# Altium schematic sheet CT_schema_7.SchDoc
size 411 x 381 mm
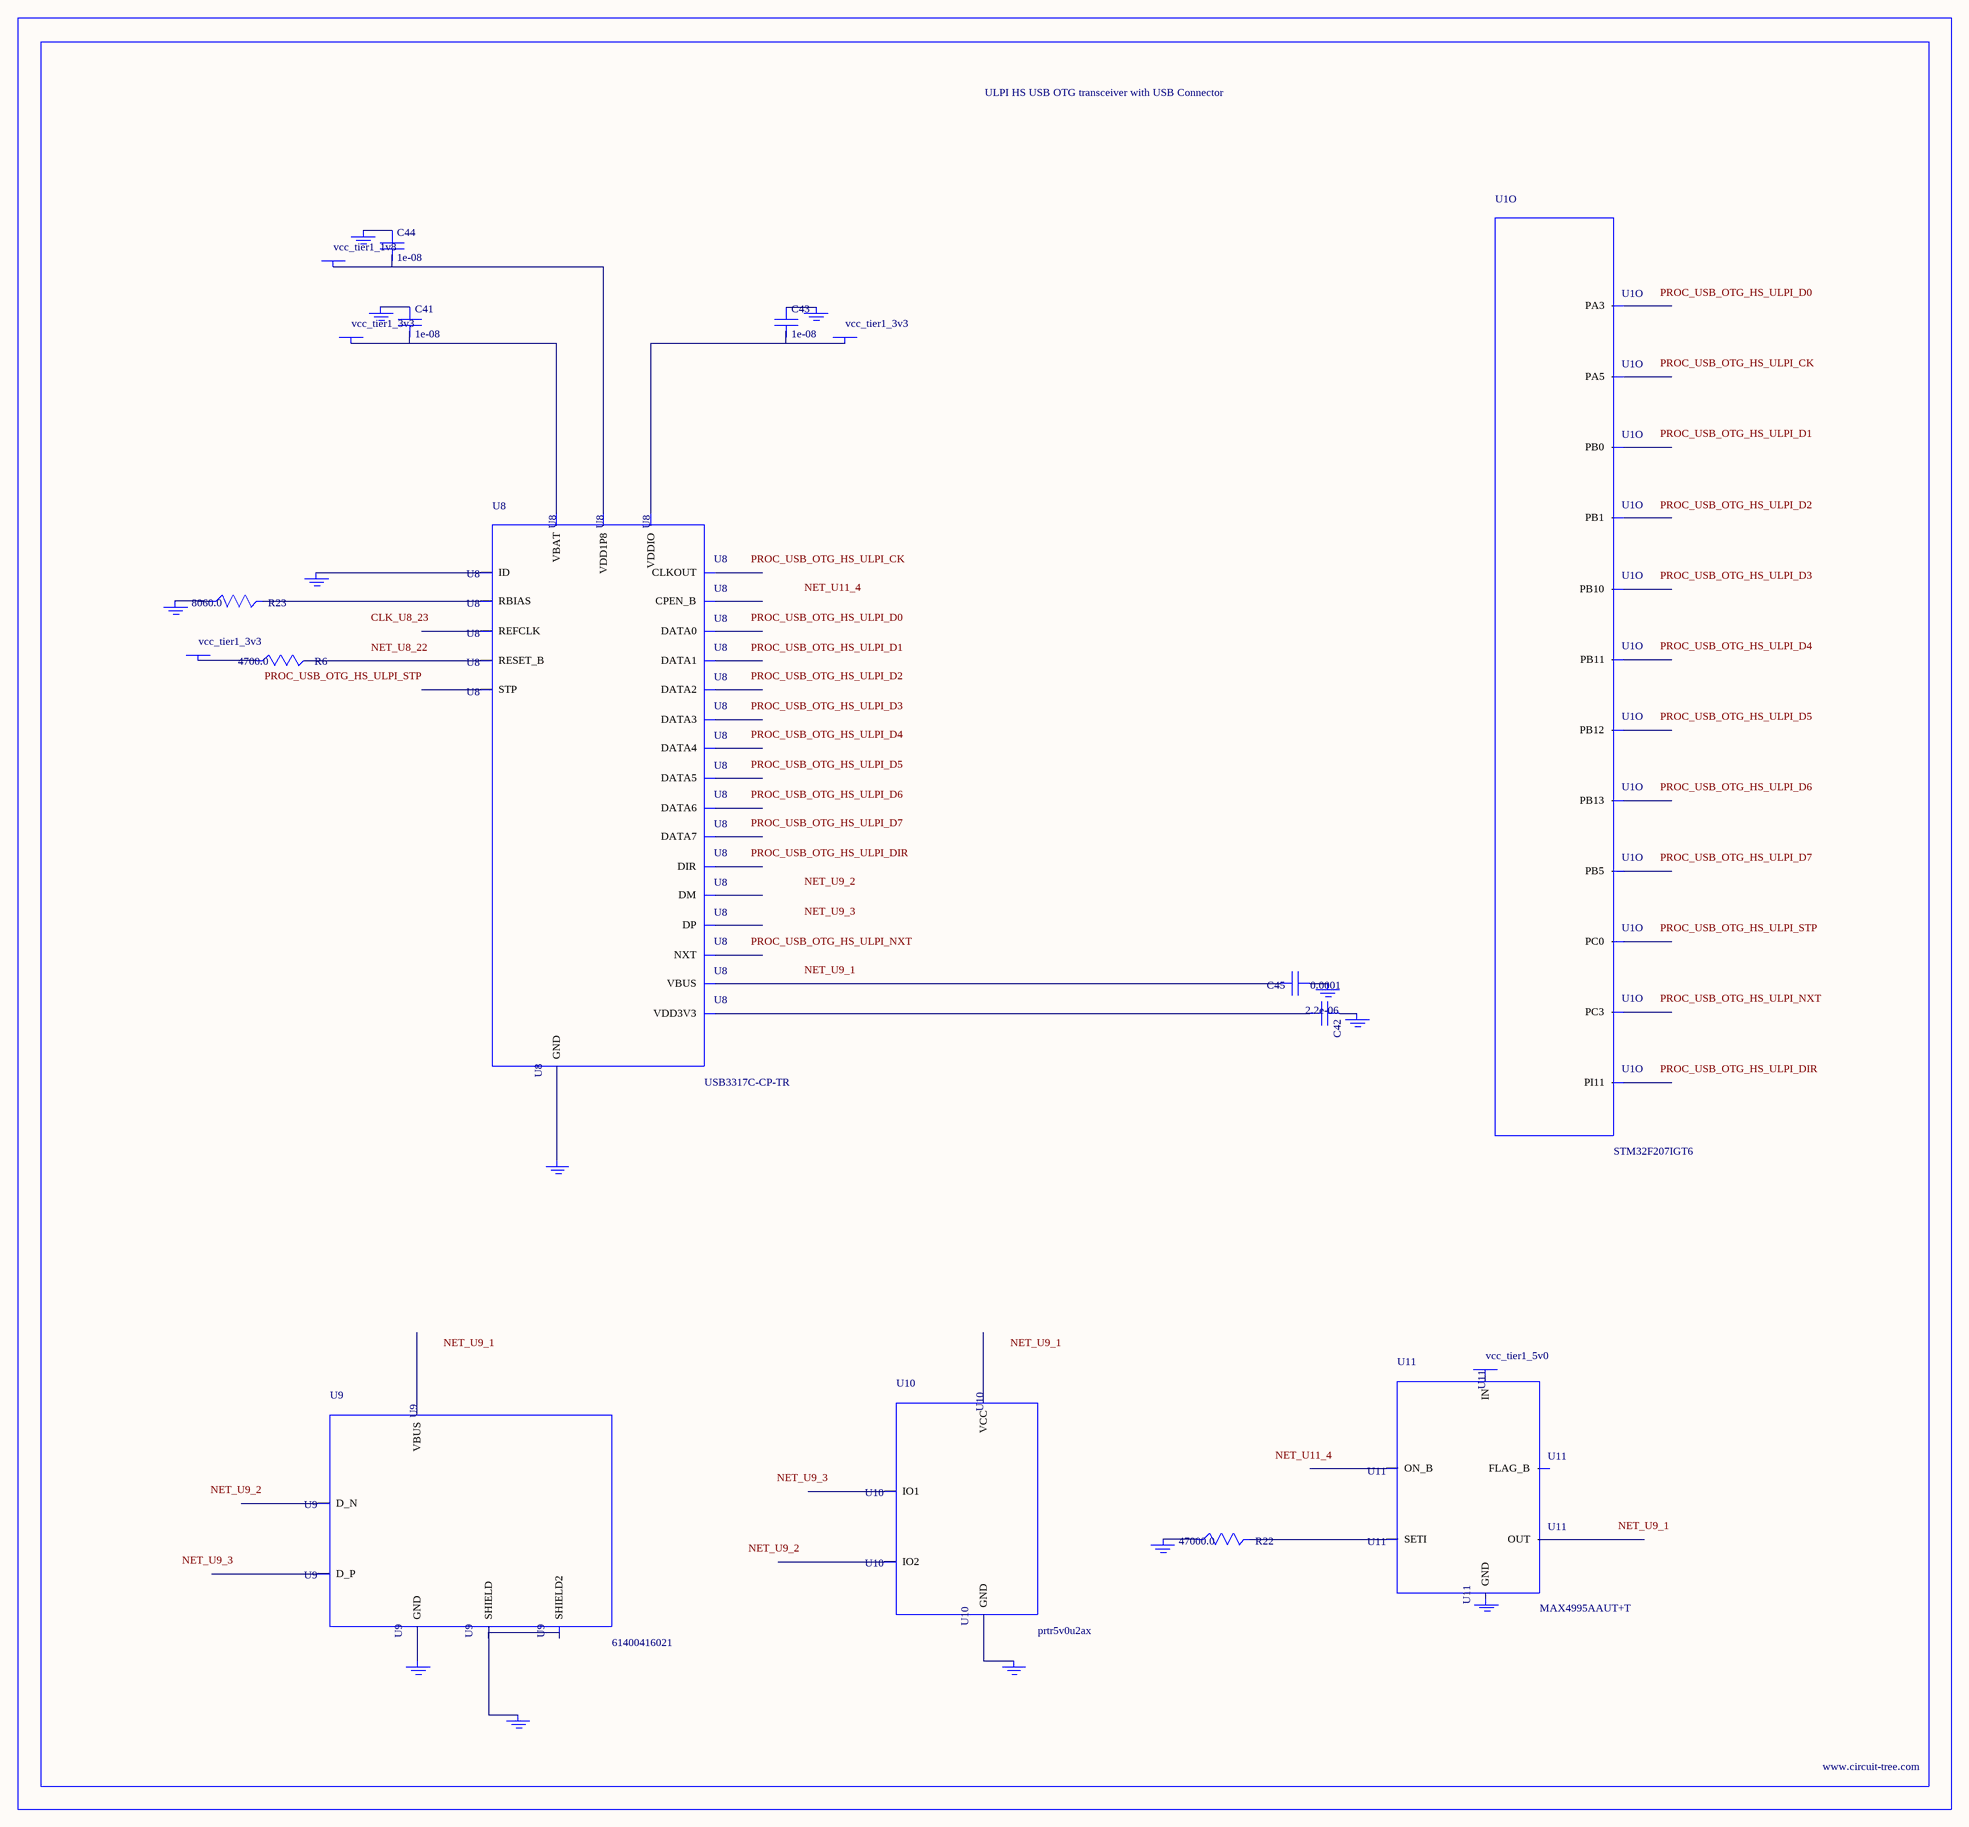
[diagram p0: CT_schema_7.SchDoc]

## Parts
BORDER6  (no value)
C41  1e-08  [C0402]
C42  2.2e-06  [C0603]
C43  1e-08  [C0402]
C44  1e-08  [C0402]
C45  0.0001  [R0603]
GND_INSTANCE_6_0  (no value)
GND_INSTANCE_6_1  (no value)
GND_INSTANCE_6_2  (no value)
GND_INSTANCE_6_3  (no value)
GND_INSTANCE_6_4  (no value)
GND_INSTANCE_6_5  (no value)
GND_INSTANCE_6_6  (no value)
GND_INSTANCE_6_7  (no value)
GND_INSTANCE_6_8  (no value)
GND_INSTANCE_6_9  (no value)
GND_INSTANCE_6_10  (no value)
GND_INSTANCE_6_11  (no value)
GND_INSTANCE_6_12  (no value)
POWER_INSTANCE_6_0  vcc_tier1_3v3
POWER_INSTANCE_6_1  vcc_tier1_3v3
POWER_INSTANCE_6_2  vcc_tier1_1v8
POWER_INSTANCE_6_3  vcc_tier1_3v3
POWER_INSTANCE_6_4  vcc_tier1_5v0
R6  4700.0  [R0603]
R22  47000.0  [R0603]
R23  8060.0  [R0603]
U1  STM32F207IGT6  [LQFP176]  (part O of 15)
U8  USB3317C-CP-TR  [QFN-24]
U9  61400416021  [USB-A-H]
U10  prtr5v0u2ax  [SOT143B]
U11  MAX4995AAUT+T  [SOT-23-6]

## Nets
NetC41_1: C41.1 GND_INSTANCE_6_2.0(GND)
NetC41_2: C41.2 POWER_INSTANCE_6_0.0(PWR) U8.3(VBAT)
NetC42_1: C42.1 GND_INSTANCE_6_3.0(GND)
NetC42_2: C42.2 U8.4(VDD3V3)
NetC43_1: C43.1 GND_INSTANCE_6_4.0(GND)
NetC43_2: C43.2 POWER_INSTANCE_6_1.0(PWR) U8.17(VDDIO)
NetC44_1: C44.1 GND_INSTANCE_6_5.0(GND)
NetC44_2: C44.2 POWER_INSTANCE_6_2.0(PWR) U8.21(VDD1P8)
NetC45_1: C45.1 GND_INSTANCE_6_1.0(GND)
NetC45_2: C45.2 U8.2(VBUS)
NetGND_INSTANCE_6_0_0: GND_INSTANCE_6_0.0(GND) U8.1(ID)
NetGND_INSTANCE_6_6_0: GND_INSTANCE_6_6.0(GND) R23.1
NetGND_INSTANCE_6_7_0: GND_INSTANCE_6_7.0(GND) U8.25(GND)
NetGND_INSTANCE_6_8_0: GND_INSTANCE_6_8.0(GND) U9.5(SHIELD) U9.6(SHIELD2)
NetGND_INSTANCE_6_9_0: GND_INSTANCE_6_9.0(GND) U9.4(GND)
NetGND_INSTANCE_6_10_0: GND_INSTANCE_6_10.0(GND) U10.1(GND)
NetGND_INSTANCE_6_11_0: GND_INSTANCE_6_11.0(GND) R22.1
NetPOWER_INSTANCE_6_3_0: POWER_INSTANCE_6_3.0(PWR) R6.1
NetR6_2: R6.2 U8.22(RESET_B)
NetR22_2: R22.2 U11.3(SETI)
NetR23_2: R23.2 U8.24(RBIAS)

Not connected (* = marked no-connect by the designer): GND_INSTANCE_6_12 0(GND); POWER_INSTANCE_6_4 0(PWR); U1 13(PI11) 32(PC0) 35(PC3) 47(PA3) 51(PA5) 56(PB0) 57(PB1) 79(PB10) 80(PB11) 92(PB12) 93(PB13) 163(PB5); U8 5(DM) 6(DP) 7(CPEN_B) 8(DATA7) 9(DATA6) 10(DATA5) 11(DATA4) 12(CLKOUT) 13(DATA3) 14(DATA2) 15(DATA1) 16(DATA0) 18(NXT) 19(DIR) 20(STP) 23(REFCLK); U9 1(VBUS) 2(D_N) 3(D_P); U10 2(IO1) 3(IO2) 4(VCC); U11 1(OUT) 2(GND) 4(ON_B) 5(IN) 6(FLAG_B)

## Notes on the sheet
- Labels drawn without touching a wire or pin: CLK_U8_23, NET_U8_22, NET_U9_1, NET_U9_2, NET_U9_3, NET_U11_4, PROC_USB_OTG_HS_ULPI_CK, PROC_USB_OTG_HS_ULPI_D0, PROC_USB_OTG_HS_ULPI_D1, PROC_USB_OTG_HS_ULPI_D2, PROC_USB_OTG_HS_ULPI_D3, PROC_USB_OTG_HS_ULPI_D4, PROC_USB_OTG_HS_ULPI_D5, PROC_USB_OTG_HS_ULPI_D6, PROC_USB_OTG_HS_ULPI_D7, PROC_USB_OTG_HS_ULPI_DIR, PROC_USB_OTG_HS_ULPI_NXT, PROC_USB_OTG_HS_ULPI_STP

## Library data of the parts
BORDER6 = BORDER_PAGE6
C41 C43 C44 = C0402C103K3RAC
C42 = C0603C225K8RACTU
C45 = C45
GND_INSTANCE_6_0-GND_INSTANCE_6_12 = GND
POWER_INSTANCE_6_0-POWER_INSTANCE_6_4 = PWR
R6 = RC0603JR-074K7L
R22 = RC0603JR-0747KL
R23 = ERJ-3EKF8061V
